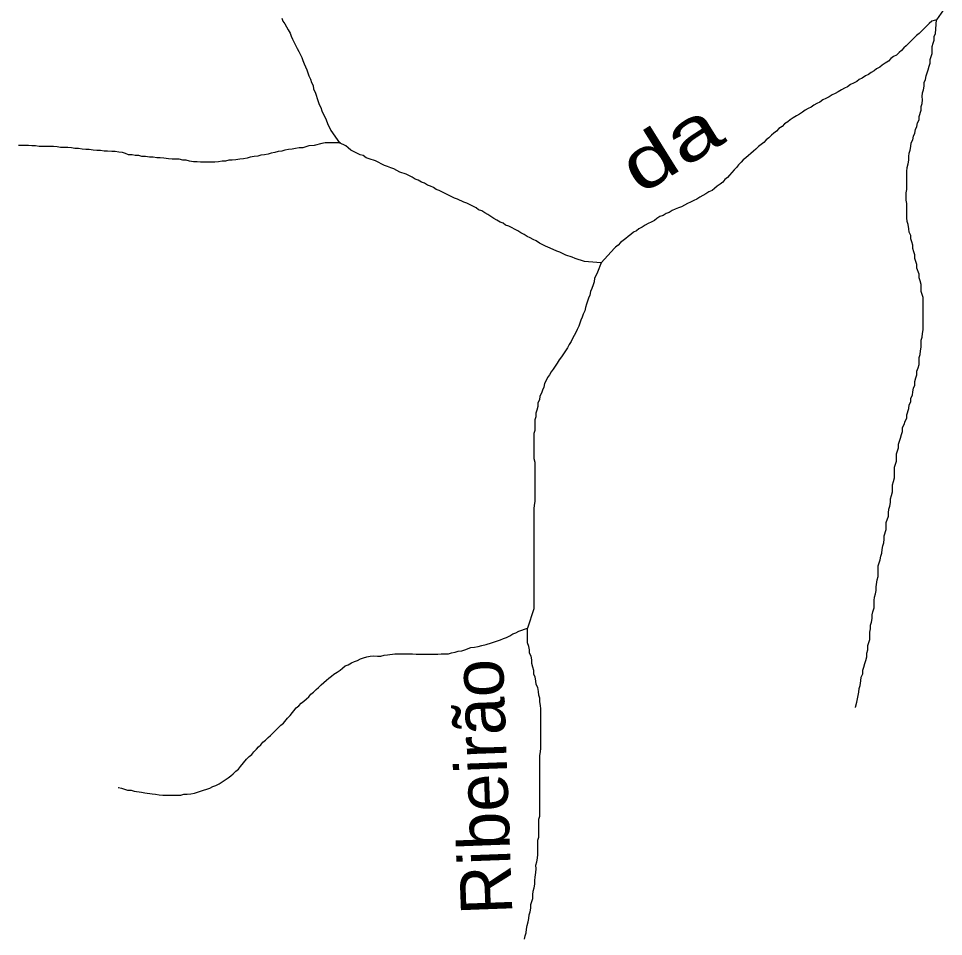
# Model space of a CAD drawing. Extents: x 652.3 to 678, y 7316.9 to 7344.9.
# Drawn here: x 674.325 to 675.766, y 7334.994 to 7336.424 of the extents above; entities that cross this region are included whole.
import ezdxf
from ezdxf.enums import TextEntityAlignment as Align

# ---------------------------------------------------------------- set-up
doc = ezdxf.new("R2010")
doc.units = 0
doc.header["$LTSCALE"] = 0.032
doc.layers.add('61', color=7, linetype='Continuous')
doc.layers.add('7', color=7, linetype='Continuous', lineweight=25)

msp = doc.modelspace()

# ---------------------------------------------------------------- linework, layer by layer
at = {"layer": '7'}
for points in [[(674.7353, 7336.4241), (674.7369, 7336.4193), (674.7401, 7336.4153), (674.7425, 7336.4106), (674.7449, 7336.4058), (674.7481, 7336.401), (674.7497, 7336.3962), (674.752, 7336.3915), (674.7592, 7336.3772), (674.7616, 7336.3724), (674.7664, 7336.3628), (674.768, 7336.3581), (674.7703, 7336.3533), (674.7719, 7336.3485), (674.7743, 7336.3437), (674.7759, 7336.339), (674.7775, 7336.3342), (674.7799, 7336.3294), (674.7815, 7336.3238), (674.7839, 7336.3191), (674.7847, 7336.3135), (674.7871, 7336.3087), (674.7918, 7336.2944), (674.7934, 7336.2896), (674.7958, 7336.2849), (674.7974, 7336.2801), (674.7998, 7336.2753), (674.8038, 7336.2673), (674.8069, 7336.2586), (674.8093, 7336.2538), (674.8117, 7336.249), (674.8253, 7336.2299)], [(675.7657, 7336.4374), (675.7546, 7336.4217), (675.7546, 7336.4217)], [(675.7546, 7336.4217), (675.7475, 7336.4193), (675.7435, 7336.4161), (675.7395, 7336.4122), (675.7355, 7336.4082), (675.7315, 7336.4042), (675.7276, 7336.4002), (675.7236, 7336.397), (675.7196, 7336.3931), (675.7156, 7336.3891), (675.7116, 7336.3851), (675.7077, 7336.3811), (675.7037, 7336.3779), (675.7005, 7336.374), (675.6965, 7336.3708), (675.6926, 7336.3668), (675.6878, 7336.3644), (675.6838, 7336.3612), (675.6798, 7336.3573), (675.675, 7336.3541)], [(675.7244, 7336.035), (675.7244, 7336.0406), (675.7228, 7336.0453), (675.7212, 7336.0501), (675.7212, 7336.0557), (675.7196, 7336.0605), (675.718, 7336.0652), (675.718, 7336.0708), (675.7164, 7336.0756), (675.7148, 7336.0804), (675.7148, 7336.0859), (675.7124, 7336.0907), (675.7116, 7336.0963), (675.7109, 7336.1026), (675.7093, 7336.1074), (675.7085, 7336.113), (675.7085, 7336.1353), (675.7077, 7336.1408), (675.7077, 7336.152), (675.7085, 7336.1575), (675.7085, 7336.1854), (675.7093, 7336.1918), (675.7109, 7336.1973), (675.7116, 7336.2029), (675.7116, 7336.2085), (675.7124, 7336.214), (675.714, 7336.2188), (675.7148, 7336.2244), (675.7156, 7336.2299), (675.718, 7336.2347), (675.7188, 7336.2403), (675.7212, 7336.2451), (675.722, 7336.2506), (675.7244, 7336.2554), (675.7252, 7336.261), (675.7276, 7336.2658), (675.7276, 7336.2713), (675.7307, 7336.2809), (675.7307, 7336.2864), (675.7323, 7336.2912), (675.7331, 7336.2968), (675.7323, 7336.3024), (675.7331, 7336.3079), (675.7347, 7336.3127), (675.7355, 7336.3183), (675.7355, 7336.3238), (675.7379, 7336.3286), (675.7387, 7336.3342), (675.7403, 7336.339), (675.7419, 7336.3437), (675.7435, 7336.3493), (675.7451, 7336.3541), (675.7451, 7336.3596), (675.7467, 7336.3644), (675.7482, 7336.3692), (675.7482, 7336.3803), (675.7498, 7336.3851), (675.7514, 7336.3899), (675.7514, 7336.3955), (675.753, 7336.4002), (675.7546, 7336.4217)], [(675.675, 7336.3541), (675.6703, 7336.3509), (675.6663, 7336.3477), (675.6615, 7336.3453), (675.6575, 7336.3421), (675.6528, 7336.3398), (675.6488, 7336.3366), (675.644, 7336.3342), (675.6392, 7336.331), (675.6345, 7336.3286), (675.6305, 7336.3254), (675.6257, 7336.323), (675.6209, 7336.3207), (675.6162, 7336.3175), (675.6114, 7336.3151), (675.6066, 7336.3127), (675.6018, 7336.3095), (675.5971, 7336.3071), (675.5923, 7336.3047), (675.5875, 7336.3016), (675.5827, 7336.2992), (675.578, 7336.2968), (675.5732, 7336.2936), (675.5684, 7336.2912), (675.5636, 7336.2888), (675.5597, 7336.2856), (675.5549, 7336.2833), (675.5501, 7336.2809), (675.5461, 7336.2777), (675.5414, 7336.2745), (675.5366, 7336.2721), (675.5318, 7336.2689), (675.527, 7336.2658), (675.5231, 7336.2626), (675.5183, 7336.2594), (675.5143, 7336.2554), (675.5095, 7336.2522), (675.5056, 7336.2482), (675.5016, 7336.2451), (675.4976, 7336.2419), (675.4936, 7336.2379), (675.4897, 7336.2347), (675.4857, 7336.2307), (675.4817, 7336.2276), (675.4777, 7336.2244), (675.4737, 7336.2204), (675.4698, 7336.2172), (675.4658, 7336.2132), (675.4618, 7336.2101), (675.4578, 7336.2069), (675.4538, 7336.2037), (675.4507, 7336.1997), (675.4467, 7336.1957), (675.4435, 7336.1918), (675.4395, 7336.1878), (675.4363, 7336.1838), (675.4324, 7336.1798), (675.4292, 7336.1758), (675.4252, 7336.1727), (675.422, 7336.1687), (675.418, 7336.1655), (675.4133, 7336.1623), (675.4093, 7336.1591), (675.4053, 7336.1559), (675.4005, 7336.1536), (675.3958, 7336.1504), (675.391, 7336.148), (675.3862, 7336.1456), (675.3814, 7336.1424), (675.3767, 7336.14), (675.3719, 7336.1376), (675.3671, 7336.1353), (675.3623, 7336.1329), (675.3576, 7336.1305), (675.3528, 7336.1289), (675.348, 7336.1265), (675.3432, 7336.1249), (675.3385, 7336.1217), (675.3337, 7336.1201), (675.3289, 7336.117), (675.3241, 7336.1154), (675.3194, 7336.1122), (675.3154, 7336.109), (675.3106, 7336.1066), (675.3058, 7336.1042), (675.3011, 7336.1018), (675.2963, 7336.0987), (675.2915, 7336.0963), (675.2875, 7336.0931), (675.2828, 7336.0907), (675.2788, 7336.0875), (675.2748, 7336.0843), (675.2708, 7336.0812), (675.2669, 7336.078), (675.2629, 7336.0748), (675.2589, 7336.0708), (675.2549, 7336.0676), (675.2533, 7336.066)], [(674.8253, 7336.2299), (674.8085, 7336.2299), (674.803, 7336.2299), (674.7974, 7336.2292), (674.7855, 7336.226), (674.7775, 7336.2252), (674.7727, 7336.2236), (674.768, 7336.222), (674.7624, 7336.222), (674.7568, 7336.2212), (674.7513, 7336.2204), (674.7457, 7336.2196), (674.7401, 7336.2188), (674.7353, 7336.2172), (674.7298, 7336.2164), (674.7242, 7336.2148), (674.7186, 7336.214), (674.7139, 7336.2124), (674.7083, 7336.2116), (674.7027, 7336.2109), (674.6979, 7336.2093), (674.6924, 7336.2085), (674.686, 7336.2077), (674.6812, 7336.2061), (674.6757, 7336.2053), (674.6701, 7336.2045), (674.6637, 7336.2037), (674.6582, 7336.2029), (674.6526, 7336.2029), (674.6478, 7336.2013), (674.6422, 7336.2013), (674.6367, 7336.2005), (674.6311, 7336.1997), (674.6088, 7336.1997), (674.6033, 7336.2005), (674.5977, 7336.2005), (674.5913, 7336.2013), (674.5865, 7336.2029), (674.581, 7336.2029), (674.5754, 7336.2045), (674.5643, 7336.2045), (674.5587, 7336.2053), (674.5515, 7336.2061), (674.546, 7336.2069), (674.5404, 7336.2069), (674.5348, 7336.2077), (674.5293, 7336.2077), (674.5229, 7336.2085), (674.5173, 7336.2085), (674.5125, 7336.2101), (674.507, 7336.2101), (674.5022, 7336.2116), (674.4966, 7336.2116), (674.4919, 7336.2132), (674.4871, 7336.2148), (674.4815, 7336.2156), (674.4759, 7336.2164), (674.4704, 7336.2164), (674.464, 7336.2172), (674.4584, 7336.2172), (674.4529, 7336.218), (674.4473, 7336.218), (674.4417, 7336.2188), (674.4354, 7336.2196), (674.4298, 7336.2196), (674.4242, 7336.2204), (674.4187, 7336.2212), (674.4131, 7336.2212), (674.4075, 7336.222), (674.4019, 7336.2228), (674.3908, 7336.2228), (674.3852, 7336.2236), (674.3797, 7336.2244), (674.3574, 7336.2244), (674.3518, 7336.2252), (674.3462, 7336.2252), (674.3407, 7336.226), (674.3252, 7336.226)], [(675.2326, 7336.043), (675.2128, 7336.0446), (675.2064, 7336.0453), (675.1921, 7336.0501), (675.1873, 7336.0517), (675.1777, 7336.0549), (675.1682, 7336.0597), (675.1634, 7336.0613), (675.1531, 7336.066), (675.1459, 7336.0692), (675.1364, 7336.074), (675.1316, 7336.0772), (675.1268, 7336.0796), (675.122, 7336.082), (675.1173, 7336.0843), (675.1125, 7336.0875), (675.1077, 7336.0899), (675.1029, 7336.0931), (675.0886, 7336.1003), (675.0838, 7336.1018), (675.0799, 7336.105), (675.0751, 7336.1066), (675.0703, 7336.1098), (675.0655, 7336.1122), (675.0608, 7336.1154), (675.056, 7336.1186), (675.0512, 7336.1209), (675.0465, 7336.1241), (675.0417, 7336.1257), (675.0377, 7336.1289), (675.0234, 7336.1361), (675.0186, 7336.1376), (675.0091, 7336.1424), (675.0043, 7336.144), (674.9804, 7336.1559), (674.9756, 7336.1575), (674.9717, 7336.1607), (674.9669, 7336.1623), (674.9621, 7336.1639), (674.9573, 7336.1671), (674.9526, 7336.1687), (674.9478, 7336.1719), (674.943, 7336.1735), (674.9382, 7336.1766), (674.9287, 7336.1814), (674.9191, 7336.1846), (674.9096, 7336.1894), (674.9048, 7336.191), (674.9, 7336.1933), (674.8953, 7336.1949), (674.8809, 7336.2021), (674.8714, 7336.2053), (674.8666, 7336.2069), (674.8619, 7336.2101), (674.8571, 7336.2116), (674.8428, 7336.2188), (674.8388, 7336.222), (674.8348, 7336.2252), (674.8253, 7336.2299)], [(674.8253, 7336.2299), (674.8269, 7336.2299), (674.8253, 7336.2299)], [(675.2533, 7336.066), (675.2326, 7336.043), (675.2326, 7336.043)], [(675.2326, 7336.043), (675.2271, 7336.0286), (675.2247, 7336.0239)], [(675.6286, 7335.3505), (675.6287, 7335.3509), (675.6305, 7335.3587), (675.6329, 7335.369), (675.6337, 7335.3746), (675.6345, 7335.3802), (675.6361, 7335.3849), (675.6369, 7335.3921), (675.6376, 7335.3977), (675.64, 7335.4032), (675.64, 7335.4088), (675.6416, 7335.4136), (675.6432, 7335.4191), (675.6448, 7335.4239), (675.6464, 7335.4295), (675.6464, 7335.4351), (675.648, 7335.4406), (675.648, 7335.447), (675.6496, 7335.4518), (675.6512, 7335.4565), (675.6512, 7335.4677), (675.652, 7335.4732), (675.652, 7335.4788), (675.6536, 7335.4836), (675.6544, 7335.4892), (675.6544, 7335.4947), (675.6559, 7335.4995), (675.6575, 7335.5059), (675.6575, 7335.517), (675.6583, 7335.5226), (675.6599, 7335.5274), (675.6607, 7335.5329), (675.6607, 7335.5385), (675.6623, 7335.5496), (675.6639, 7335.5544), (675.6639, 7335.5711), (675.6671, 7335.5807), (675.6679, 7335.5862), (675.6695, 7335.591), (675.6703, 7335.5966), (675.6711, 7335.6022), (675.6727, 7335.6069), (675.6735, 7335.6125), (675.6735, 7335.6181), (675.6766, 7335.6276), (675.6766, 7335.6388), (675.6798, 7335.6483), (675.6798, 7335.6539), (675.6806, 7335.6594), (675.6822, 7335.6642), (675.683, 7335.6698), (675.683, 7335.6754), (675.6846, 7335.6809), (675.6862, 7335.6865), (675.6862, 7335.6976), (675.6878, 7335.7024), (675.6894, 7335.708), (675.6894, 7335.7247), (675.691, 7335.7295), (675.6926, 7335.7342), (675.6926, 7335.7454), (675.6957, 7335.7549), (675.6957, 7335.7605), (675.6973, 7335.7653), (675.6989, 7335.77), (675.7005, 7335.7756), (675.7021, 7335.7804), (675.7021, 7335.7868), (675.7045, 7335.7915), (675.7061, 7335.7963), (675.7085, 7335.8011), (675.7085, 7335.8066), (675.7116, 7335.8162), (675.7124, 7335.8218), (675.7148, 7335.8265), (675.7148, 7335.8321), (675.7172, 7335.8369), (675.718, 7335.8424), (675.7188, 7335.848), (675.7212, 7335.8528), (675.7212, 7335.8584), (675.7228, 7335.8639), (675.7244, 7335.8687), (675.7244, 7335.8743), (675.726, 7335.8798), (675.7276, 7335.8846), (675.7276, 7335.8958), (675.7292, 7335.9005), (675.7299, 7335.9061), (675.7307, 7335.9117), (675.7307, 7335.9228), (675.7323, 7335.9276), (675.7331, 7335.9332), (675.7339, 7335.9387), (675.7339, 7335.9889), (675.7307, 7335.9984), (675.7307, 7336.0095), (675.7292, 7336.0151), (675.7276, 7336.0199), (675.7276, 7336.0255), (675.7244, 7336.035)], [(675.2247, 7336.0239), (675.2223, 7336.0191), (675.2215, 7336.0135), (675.2199, 7336.0087), (675.2183, 7336.0032), (675.2159, 7335.9984), (675.2151, 7335.9928), (675.2128, 7335.9881), (675.2112, 7335.9833), (675.2096, 7335.9785), (675.208, 7335.9737), (675.2072, 7335.9682), (675.2048, 7335.9634), (675.2032, 7335.9586), (675.2008, 7335.9538), (675.1992, 7335.9491), (675.1976, 7335.9443), (675.1952, 7335.9395), (675.1929, 7335.9347), (675.1905, 7335.93), (675.1881, 7335.9252), (675.1857, 7335.9204), (675.1825, 7335.9157), (675.1801, 7335.9109), (675.1769, 7335.9061), (675.1738, 7335.9013), (675.1706, 7335.8966), (675.1674, 7335.8918), (675.1642, 7335.887), (675.161, 7335.8822), (675.1578, 7335.8775), (675.1547, 7335.8735), (675.1523, 7335.8687), (675.1491, 7335.8647), (675.1467, 7335.86), (675.1443, 7335.8552), (675.1435, 7335.8496), (675.1411, 7335.8448), (675.1395, 7335.8401), (675.1372, 7335.8353), (675.1364, 7335.8297), (675.134, 7335.8249), (675.134, 7335.8194), (675.1324, 7335.8138), (675.1308, 7335.809), (675.1308, 7335.8035), (675.1292, 7335.7987), (675.1292, 7335.7931), (675.1292, 7335.7875), (675.1292, 7335.782), (675.1276, 7335.7772), (675.1276, 7335.7716), (675.1276, 7335.7661), (675.1276, 7335.7605), (675.1276, 7335.7549), (675.1276, 7335.7494), (675.1276, 7335.7438), (675.1276, 7335.7382), (675.1292, 7335.7326), (675.1292, 7335.7271), (675.1292, 7335.7215), (675.1292, 7335.7159), (675.1292, 7335.7104), (675.1292, 7335.7048), (675.1292, 7335.6992), (675.1292, 7335.6937), (675.1292, 7335.6881), (675.1292, 7335.6825), (675.1292, 7335.6769), (675.1292, 7335.6714), (675.1284, 7335.6658), (675.1276, 7335.6602), (675.1276, 7335.6547), (675.1276, 7335.6491), (675.1276, 7335.6435), (675.1276, 7335.638), (675.1276, 7335.6324), (675.1276, 7335.6268), (675.1276, 7335.6212), (675.1276, 7335.6157), (675.1276, 7335.6101), (675.1276, 7335.6045), (675.1276, 7335.599), (675.1276, 7335.5934), (675.1276, 7335.5878), (675.1276, 7335.5823), (675.1276, 7335.5767), (675.1276, 7335.5711), (675.1276, 7335.5655), (675.1276, 7335.56), (675.1276, 7335.5544), (675.1276, 7335.5488), (675.1276, 7335.5433), (675.1276, 7335.5377), (675.1276, 7335.5321), (675.1276, 7335.5266), (675.1276, 7335.521), (675.1276, 7335.5154), (675.1276, 7335.5099), (675.1276, 7335.5043), (675.1181, 7335.474)], [(674.5006, 7335.2218), (674.5054, 7335.2202), (674.5165, 7335.2186), (674.5221, 7335.2178), (674.5332, 7335.2162), (674.5388, 7335.2154), (674.5444, 7335.2147), (674.5499, 7335.2139), (674.5778, 7335.2139), (674.5826, 7335.2154), (674.5881, 7335.2154), (674.5937, 7335.2162), (674.5993, 7335.217), (674.604, 7335.2186), (674.6088, 7335.2202), (674.6231, 7335.225), (674.6279, 7335.2274), (674.6327, 7335.229), (674.6375, 7335.2314), (674.6422, 7335.2345), (674.647, 7335.2377), (674.6518, 7335.2409), (674.6558, 7335.2441), (674.6597, 7335.2473), (674.6637, 7335.2513), (674.6677, 7335.2544), (674.6709, 7335.2584), (674.6804, 7335.2703), (674.6844, 7335.2743), (674.6884, 7335.2775), (674.6916, 7335.2815), (674.6956, 7335.2855), (674.6987, 7335.2894), (674.7027, 7335.2926), (674.7059, 7335.2966), (674.7099, 7335.2998), (674.7139, 7335.3038), (674.7178, 7335.307), (674.7337, 7335.3229), (674.7377, 7335.326), (674.7441, 7335.334), (674.7481, 7335.338), (674.7576, 7335.3499), (674.7616, 7335.3531), (674.7656, 7335.3571), (674.7696, 7335.3603), (674.7735, 7335.3642), (674.7775, 7335.3674), (674.7807, 7335.3714), (674.7847, 7335.3746), (674.7886, 7335.3786), (674.7926, 7335.3817), (674.7966, 7335.3857), (674.8006, 7335.3897), (674.8046, 7335.3929), (674.8085, 7335.3961), (674.8125, 7335.3993), (674.8165, 7335.4024), (674.8213, 7335.4056), (674.826, 7335.4088), (674.83, 7335.412), (674.834, 7335.4152), (674.8388, 7335.4168), (674.8436, 7335.4199), (674.8483, 7335.4223), (674.8531, 7335.4239), (674.8579, 7335.4263), (674.8626, 7335.4279), (674.8674, 7335.4295), (674.873, 7335.4303), (674.8786, 7335.4311), (674.8841, 7335.4303), (674.8897, 7335.4303), (674.8945, 7335.4319), (674.9, 7335.4327), (674.9112, 7335.4343), (674.939, 7335.4343), (674.9446, 7335.4335), (674.978, 7335.4335), (674.9836, 7335.4343), (674.9947, 7335.4343), (674.9995, 7335.4359), (675.0051, 7335.4366), (675.0098, 7335.4382), (675.0154, 7335.439), (675.0202, 7335.4406), (675.0297, 7335.4438), (675.0353, 7335.4446), (675.0409, 7335.4454), (675.0465, 7335.447), (675.0536, 7335.4486), (675.0616, 7335.451), (675.0711, 7335.4542), (675.0759, 7335.4557), (675.0807, 7335.4581), (675.0854, 7335.4597), (675.0902, 7335.4621), (675.095, 7335.4653), (675.0998, 7335.4669), (675.1045, 7335.4693), (675.1181, 7335.474)], [(675.1372, 7335.365), (675.1356, 7335.3698), (675.1348, 7335.3754), (675.134, 7335.3817), (675.1316, 7335.3865), (675.1308, 7335.3921), (675.13, 7335.3977), (675.1276, 7335.4024), (675.1276, 7335.408), (675.126, 7335.4136), (675.1244, 7335.4191), (675.1244, 7335.4247), (675.1236, 7335.4303), (675.1212, 7335.4351), (675.1212, 7335.4406), (675.1197, 7335.4454), (675.1181, 7335.451), (675.1181, 7335.4605), (675.1181, 7335.474), (675.1181, 7335.474)], [(675.1133, 7334.9895), (675.1141, 7334.995), (675.1157, 7334.9998), (675.1165, 7335.0054), (675.1173, 7335.011), (675.1189, 7335.0165), (675.1197, 7335.0221), (675.1205, 7335.0277), (675.122, 7335.0324), (675.1228, 7335.038), (675.1228, 7335.0436), (675.1244, 7335.0484), (675.126, 7335.0531), (675.126, 7335.0587), (675.1268, 7335.0643), (675.1284, 7335.0698), (675.1292, 7335.0754), (675.1292, 7335.081), (675.13, 7335.0865), (675.1308, 7335.0937), (675.1316, 7335.0993), (675.1308, 7335.1048), (675.1324, 7335.1104), (675.1332, 7335.116), (675.134, 7335.1216), (675.134, 7335.1438), (675.1356, 7335.1486), (675.1356, 7335.1765), (675.1372, 7335.1812), (675.1372, 7335.2759), (675.138, 7335.2815), (675.1388, 7335.2871), (675.1388, 7335.3483), (675.138, 7335.3539), (675.1372, 7335.3595), (675.1372, 7335.365)], [(674.4803, 7335.2259), (674.4807, 7335.2258), (674.4855, 7335.225), (674.495, 7335.2218), (674.5006, 7335.2218)]]:
    msp.add_lwpolyline(points, dxfattribs=at)

# ---------------------------------------------------------------- texts
at = {"layer": '61', "width": 1.35}
msp.add_text('da', height=0.08, rotation=31.917, dxfattribs=at).set_placement((675.3614, 7336.1905), align=Align.CENTER)
at = {"layer": '61'}
msp.add_text('Ribeirão', height=0.08, rotation=92.137, dxfattribs=at).set_placement((675.087, 7335.2281), align=Align.CENTER)

doc.saveas('drawing.dxf')
